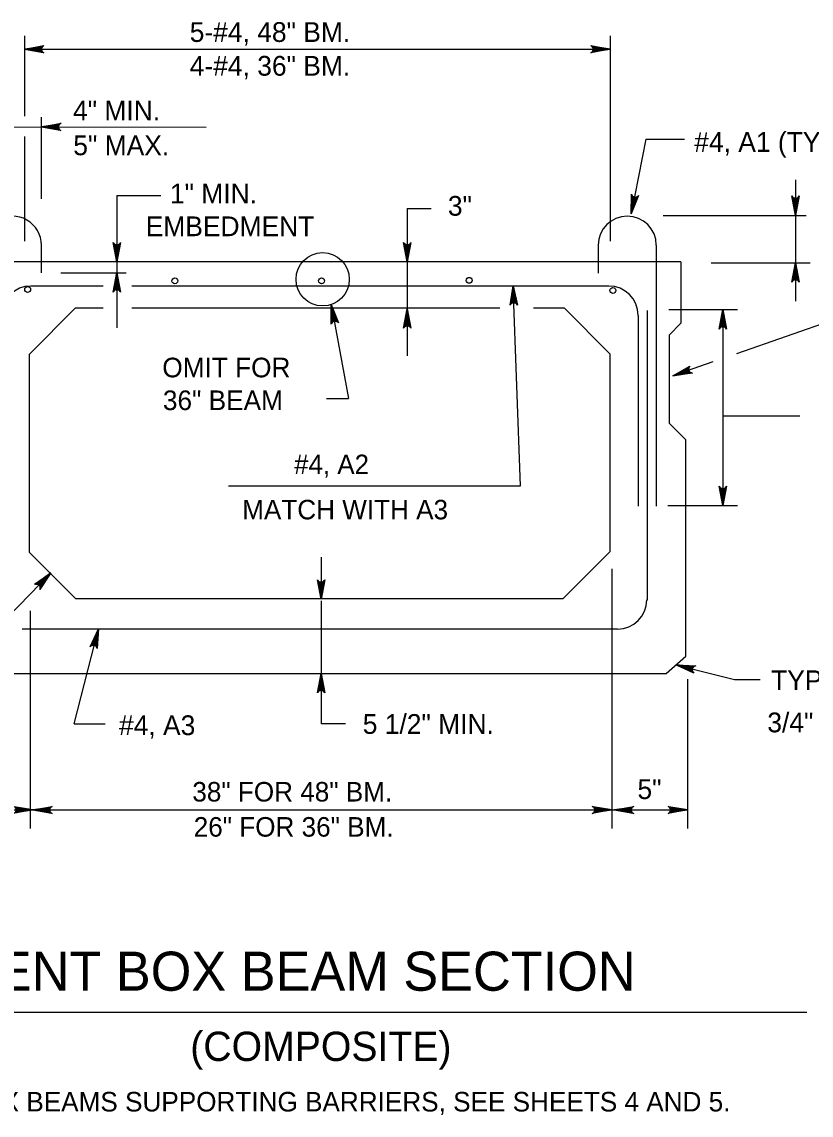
# Model space of a CAD drawing. Extents: x 639331 to 643089, y 299088 to 300975.
# Drawn here: x 640804.7 to 640925.9, y 299972.3 to 300140.1 of the extents above; entities that cross this region are included whole.
import ezdxf

# ---------------------------------------------------------------- set-up
doc = ezdxf.new("R2010")
doc.units = 0
doc.layers.add('1', color=7, linetype='Continuous')

msp = doc.modelspace()

# ---------------------------------------------------------------- linework, layer by layer
at = {"layer": '1'}
for p, q in [((640805.1, 300137.92), (640805.1, 300125.6)), ((640895.02, 300137.92), (640895.02, 300106.4)), ((640805.1, 300135.87), (640895.02, 300135.87)), ((640807.7, 300112.91), (640807.72, 300125.45)), ((640790.04, 300123.99), (640833.01, 300123.91)), ((640805.1, 300122.51), (640805.1, 300106.4)), ((640900.5, 300122.06), (640898.25, 300110.62)), ((640900.5, 300122.06), (640906.42, 300122.06)), ((640923.49, 300115.86), (640923.49, 300110.38)), ((640819.29, 300113.41), (640826.03, 300113.41)), ((640819.29, 300113.41), (640819.29, 300101.58)), ((640863.88, 300111.46), (640867.54, 300111.46)), ((640863.88, 300111.46), (640863.88, 300103.25)), ((640903.15, 300110.38), (640925.12, 300110.38)), ((640923.49, 300110.38), (640923.49, 300103.12)), ((640807.68, 300105.81), (640807.68, 300101.58)), ((640893.19, 300105.82), (640893.19, 300101.53)), ((640902.11, 300105.81), (640902.11, 300065.74)), ((640905.9, 300103.25), (640794.85, 300103.25)), ((640863.88, 300103.25), (640863.88, 300096.17)), ((640905.9, 300103.25), (640905.9, 300093.82)), ((640910.56, 300103.12), (640925.73, 300103.12)), ((640923.49, 300103.12), (640923.49, 300097.21)), ((640810.68, 300101.58), (640820.72, 300101.58)), ((640819.29, 300101.58), (640819.29, 300093.14)), ((640828.21, 300100.67), (640828.21, 300100.67)), ((640850.82, 300100.55), (640850.82, 300100.55)), ((640873.3, 300100.42), (640873.3, 300100.42)), ((640805.73, 300099.33), (640805.73, 300099.33)), ((640806.08, 300099.58), (640817.16, 300099.58)), ((640821.58, 300099.58), (640894.81, 300099.58)), ((640881.27, 300068.86), (640880.12, 300099.58)), ((640895.91, 300098.83), (640895.91, 300098.83)), ((640805.86, 300089.1), (640812.93, 300096.17)), ((640812.93, 300096.17), (640817.16, 300096.17)), ((640821.58, 300096.17), (640878.11, 300096.17)), ((640852.21, 300096.71), (640854.86, 300082.28)), ((640863.88, 300096.17), (640863.88, 300088.85)), ((640883.27, 300096.17), (640887.95, 300096.17)), ((640887.95, 300096.17), (640895.02, 300089.1)), ((640900.71, 300095.8), (640900.71, 300051.34)), ((640904.03, 300095.92), (640914.6, 300095.92)), ((640912.33, 300095.92), (640912.33, 300065.85)), ((640932.22, 300095.37), (640914.43, 300089.15)), ((640899.31, 300095.04), (640899.31, 300065.74)), ((640905.9, 300093.82), (640904.11, 300092.02)), ((640904.11, 300092.02), (640904.11, 300078.48)), ((640805.86, 300058.67), (640805.86, 300089.1)), ((640895.02, 300058.79), (640895.02, 300089.1)), ((640910.79, 300087.88), (640904.64, 300085.74)), ((640851.45, 300082.28), (640854.86, 300082.28)), ((640906.64, 300075.94), (640904.11, 300078.48)), ((640912.33, 300079.63), (640924.17, 300079.63)), ((640906.64, 300042.75), (640906.64, 300075.94)), ((640836.42, 300068.86), (640881.27, 300068.86)), ((640903.86, 300065.85), (640914.6, 300065.85)), ((640805.86, 300058.67), (640812.93, 300051.59)), ((640887.82, 300051.59), (640895.02, 300058.79)), ((640850.63, 300057.93), (640850.63, 300051.47)), ((640809.14, 300055.51), (640786.72, 300032.44)), ((640895.28, 300056.14), (640895.28, 300016.29)), ((640812.93, 300051.59), (640887.82, 300051.59)), ((640850.63, 300051.21), (640850.63, 300040.1)), ((640805.99, 300049.7), (640805.99, 300016.29)), ((640804.72, 300046.92), (640896.16, 300046.92)), ((640812.75, 300032.35), (640816.47, 300046.92)), ((640903.61, 300040.1), (640906.64, 300042.75)), ((640797.14, 300040.1), (640903.61, 300040.1)), ((640850.63, 300040.1), (640850.63, 300039.97)), ((640850.63, 300040.1), (640850.63, 300032.35)), ((640905.13, 300041.43), (640914.12, 300039.15)), ((640906.89, 300039.19), (640906.89, 300016.29)), ((640914.12, 300039.15), (640918.05, 300039.15)), ((640812.75, 300032.35), (640817.48, 300032.35)), ((640854.39, 300032.35), (640850.63, 300032.35)), ((640794.37, 300019.13), (640806.36, 300019.13)), ((640806.36, 300019.13), (640895.65, 300019.13)), ((640895.65, 300019.13), (640906.89, 300019.13)), ((640772.36, 299988.08), (640925.24, 299988.08))]:
    msp.add_line(p, q, dxfattribs=at)
for points in [[(640805.1, 300135.87), (640808.08, 300136.43), (640807.97, 300136.35), (640807.85, 300136.27), (640807.8, 300136.17), (640807.74, 300136.07), (640807.72, 300135.97), (640807.7, 300135.87), (640807.72, 300135.77), (640807.74, 300135.67), (640807.8, 300135.57), (640807.85, 300135.47), (640807.97, 300135.39), (640808.08, 300135.31), (640805.1, 300135.87), (640807.97, 300135.39), (640807.85, 300135.47), (640805.1, 300135.87), (640807.8, 300135.57), (640807.74, 300135.67), (640805.1, 300135.87), (640807.72, 300135.77), (640807.7, 300135.87), (640805.1, 300135.87), (640807.72, 300135.97), (640807.74, 300136.07), (640805.1, 300135.87), (640807.8, 300136.17), (640807.85, 300136.27), (640805.1, 300135.87), (640807.97, 300136.35)], [(640895.02, 300135.87), (640892.04, 300135.31), (640892.16, 300135.39), (640892.27, 300135.47), (640892.33, 300135.57), (640892.39, 300135.67), (640892.41, 300135.77), (640892.42, 300135.87), (640892.41, 300135.97), (640892.39, 300136.07), (640892.33, 300136.17), (640892.27, 300136.27), (640892.16, 300136.35), (640892.04, 300136.43), (640895.02, 300135.87), (640892.16, 300136.35), (640892.27, 300136.27), (640895.02, 300135.87), (640892.33, 300136.17), (640892.39, 300136.07), (640895.02, 300135.87), (640892.41, 300135.97), (640892.42, 300135.87), (640895.02, 300135.87), (640892.41, 300135.77), (640892.39, 300135.67), (640895.02, 300135.87), (640892.33, 300135.57), (640892.27, 300135.47), (640895.02, 300135.87), (640892.16, 300135.39)], [(640807.72, 300123.96), (640810.71, 300124.51), (640810.59, 300124.44), (640810.48, 300124.36), (640810.42, 300124.26), (640810.36, 300124.16), (640810.34, 300124.06), (640810.32, 300123.96), (640810.34, 300123.86), (640810.36, 300123.76), (640810.42, 300123.66), (640810.47, 300123.56), (640810.59, 300123.48), (640810.7, 300123.4), (640807.72, 300123.96), (640810.59, 300123.48), (640810.47, 300123.56), (640807.72, 300123.96), (640810.42, 300123.66), (640810.36, 300123.76), (640807.72, 300123.96), (640810.34, 300123.86), (640810.32, 300123.96), (640807.72, 300123.96), (640810.34, 300124.06), (640810.36, 300124.16), (640807.72, 300123.96), (640810.42, 300124.26), (640810.48, 300124.36), (640807.72, 300123.96), (640810.59, 300124.44)], [(640898.25, 300110.62), (640898.28, 300113.65), (640898.34, 300113.53), (640898.39, 300113.4), (640898.48, 300113.32), (640898.57, 300113.24), (640898.66, 300113.21), (640898.75, 300113.17), (640898.86, 300113.17), (640898.96, 300113.17), (640899.07, 300113.2), (640899.18, 300113.24), (640899.28, 300113.34), (640899.38, 300113.44), (640898.25, 300110.62), (640899.28, 300113.34), (640899.18, 300113.24), (640898.25, 300110.62), (640899.07, 300113.2), (640898.96, 300113.17), (640898.25, 300110.62), (640898.86, 300113.17), (640898.75, 300113.17), (640898.25, 300110.62), (640898.66, 300113.21), (640898.57, 300113.24), (640898.25, 300110.62), (640898.48, 300113.32), (640898.39, 300113.4), (640898.25, 300110.62), (640898.34, 300113.53)], [(640923.49, 300110.38), (640922.93, 300113.36), (640923.01, 300113.25), (640923.09, 300113.13), (640923.19, 300113.07), (640923.29, 300113.01), (640923.39, 300113), (640923.49, 300112.98), (640923.59, 300113), (640923.69, 300113.01), (640923.79, 300113.07), (640923.89, 300113.13), (640923.97, 300113.25), (640924.05, 300113.36), (640923.49, 300110.38), (640923.97, 300113.25), (640923.89, 300113.13), (640923.49, 300110.38), (640923.79, 300113.07), (640923.69, 300113.01), (640923.49, 300110.38), (640923.59, 300113), (640923.49, 300112.98), (640923.49, 300110.38), (640923.39, 300113), (640923.29, 300113.01), (640923.49, 300110.38), (640923.19, 300113.07), (640923.09, 300113.13), (640923.49, 300110.38), (640923.01, 300113.25)], [(640819.29, 300103.25), (640818.73, 300106.23), (640818.81, 300106.12), (640818.89, 300106), (640818.99, 300105.94), (640819.09, 300105.88), (640819.19, 300105.86), (640819.29, 300105.85), (640819.39, 300105.86), (640819.49, 300105.88), (640819.59, 300105.94), (640819.69, 300106), (640819.77, 300106.12), (640819.85, 300106.23), (640819.29, 300103.25), (640819.77, 300106.12), (640819.69, 300106), (640819.29, 300103.25), (640819.59, 300105.94), (640819.49, 300105.88), (640819.29, 300103.25), (640819.39, 300105.86), (640819.29, 300105.85), (640819.29, 300103.25), (640819.19, 300105.86), (640819.09, 300105.88), (640819.29, 300103.25), (640818.99, 300105.94), (640818.89, 300106), (640819.29, 300103.25), (640818.81, 300106.12)], [(640863.88, 300103.25), (640863.32, 300106.23), (640863.4, 300106.12), (640863.48, 300106), (640863.58, 300105.94), (640863.68, 300105.88), (640863.78, 300105.86), (640863.88, 300105.85), (640863.98, 300105.86), (640864.08, 300105.88), (640864.18, 300105.94), (640864.28, 300106), (640864.36, 300106.12), (640864.44, 300106.23), (640863.88, 300103.25), (640864.36, 300106.12), (640864.28, 300106), (640863.88, 300103.25), (640864.18, 300105.94), (640864.08, 300105.88), (640863.88, 300103.25), (640863.98, 300105.86), (640863.88, 300105.85), (640863.88, 300103.25), (640863.78, 300105.86), (640863.68, 300105.88), (640863.88, 300103.25), (640863.58, 300105.94), (640863.48, 300106), (640863.88, 300103.25), (640863.4, 300106.12)], [(640923.49, 300103.12), (640924.05, 300100.14), (640923.97, 300100.25), (640923.89, 300100.37), (640923.79, 300100.43), (640923.69, 300100.49), (640923.59, 300100.5), (640923.49, 300100.52), (640923.39, 300100.5), (640923.29, 300100.49), (640923.19, 300100.43), (640923.09, 300100.37), (640923.01, 300100.25), (640922.93, 300100.14), (640923.49, 300103.12), (640923.01, 300100.25), (640923.09, 300100.37), (640923.49, 300103.12), (640923.19, 300100.43), (640923.29, 300100.49), (640923.49, 300103.12), (640923.39, 300100.5), (640923.49, 300100.52), (640923.49, 300103.12), (640923.59, 300100.5), (640923.69, 300100.49), (640923.49, 300103.12), (640923.79, 300100.43), (640923.89, 300100.37), (640923.49, 300103.12), (640923.97, 300100.25)], [(640819.29, 300101.58), (640819.85, 300098.6), (640819.77, 300098.72), (640819.69, 300098.83), (640819.59, 300098.89), (640819.49, 300098.95), (640819.39, 300098.97), (640819.29, 300098.98), (640819.19, 300098.97), (640819.09, 300098.95), (640818.99, 300098.89), (640818.89, 300098.83), (640818.81, 300098.72), (640818.73, 300098.6), (640819.29, 300101.58), (640818.81, 300098.72), (640818.89, 300098.83), (640819.29, 300101.58), (640818.99, 300098.89), (640819.09, 300098.95), (640819.29, 300101.58), (640819.19, 300098.97), (640819.29, 300098.98), (640819.29, 300101.58), (640819.39, 300098.97), (640819.49, 300098.95), (640819.29, 300101.58), (640819.59, 300098.89), (640819.69, 300098.83), (640819.29, 300101.58), (640819.77, 300098.72)], [(640880.12, 300099.58), (640880.79, 300096.62), (640880.71, 300096.74), (640880.62, 300096.85), (640880.52, 300096.9), (640880.42, 300096.96), (640880.32, 300096.97), (640880.22, 300096.99), (640880.12, 300096.97), (640880.02, 300096.94), (640879.92, 300096.88), (640879.82, 300096.82), (640879.75, 300096.7), (640879.67, 300096.58), (640880.12, 300099.58), (640879.75, 300096.7), (640879.82, 300096.82), (640880.12, 300099.58), (640879.92, 300096.88), (640880.02, 300096.94), (640880.12, 300099.58), (640880.12, 300096.97), (640880.22, 300096.99), (640880.12, 300099.58), (640880.32, 300096.97), (640880.42, 300096.96), (640880.12, 300099.58), (640880.52, 300096.9), (640880.62, 300096.85), (640880.12, 300099.58), (640880.71, 300096.74)], [(640852.21, 300096.71), (640853.3, 300093.87), (640853.2, 300093.97), (640853.1, 300094.07), (640852.99, 300094.11), (640852.88, 300094.15), (640852.78, 300094.15), (640852.68, 300094.15), (640852.59, 300094.11), (640852.49, 300094.08), (640852.4, 300094), (640852.32, 300093.93), (640852.26, 300093.8), (640852.2, 300093.67), (640852.21, 300096.71), (640852.26, 300093.8), (640852.32, 300093.93), (640852.21, 300096.71), (640852.4, 300094), (640852.49, 300094.08), (640852.21, 300096.71), (640852.59, 300094.11), (640852.68, 300094.15), (640852.21, 300096.71), (640852.78, 300094.15), (640852.88, 300094.15), (640852.21, 300096.71), (640852.99, 300094.11), (640853.1, 300094.07), (640852.21, 300096.71), (640853.2, 300093.97)], [(640863.88, 300096.05), (640864.44, 300093.07), (640864.36, 300093.18), (640864.28, 300093.3), (640864.18, 300093.35), (640864.08, 300093.41), (640863.98, 300093.43), (640863.88, 300093.45), (640863.78, 300093.43), (640863.68, 300093.41), (640863.58, 300093.35), (640863.48, 300093.3), (640863.4, 300093.18), (640863.32, 300093.07), (640863.88, 300096.05), (640863.4, 300093.18), (640863.48, 300093.3), (640863.88, 300096.05), (640863.58, 300093.35), (640863.68, 300093.41), (640863.88, 300096.05), (640863.78, 300093.43), (640863.88, 300093.45), (640863.88, 300096.05), (640863.98, 300093.43), (640864.08, 300093.41), (640863.88, 300096.05), (640864.18, 300093.35), (640864.28, 300093.3), (640863.88, 300096.05), (640864.36, 300093.18)], [(640912.33, 300095.92), (640912.88, 300092.94), (640912.81, 300093.05), (640912.73, 300093.17), (640912.63, 300093.23), (640912.53, 300093.29), (640912.43, 300093.3), (640912.33, 300093.32), (640912.23, 300093.3), (640912.13, 300093.29), (640912.03, 300093.23), (640911.93, 300093.17), (640911.85, 300093.05), (640911.77, 300092.94), (640912.33, 300095.92), (640911.85, 300093.05), (640911.93, 300093.17), (640912.33, 300095.92), (640912.03, 300093.23), (640912.13, 300093.29), (640912.33, 300095.92), (640912.23, 300093.3), (640912.33, 300093.32), (640912.33, 300095.92), (640912.43, 300093.3), (640912.53, 300093.29), (640912.33, 300095.92), (640912.63, 300093.23), (640912.73, 300093.17), (640912.33, 300095.92), (640912.81, 300093.05)], [(640904.64, 300085.74), (640907.28, 300087.25), (640907.19, 300087.13), (640907.11, 300087.02), (640907.09, 300086.91), (640907.07, 300086.79), (640907.08, 300086.69), (640907.1, 300086.59), (640907.15, 300086.5), (640907.2, 300086.42), (640907.29, 300086.34), (640907.38, 300086.27), (640907.51, 300086.23), (640907.65, 300086.19), (640904.64, 300085.74), (640907.51, 300086.23), (640907.38, 300086.27), (640904.64, 300085.74), (640907.29, 300086.34), (640907.2, 300086.42), (640904.64, 300085.74), (640907.15, 300086.5), (640907.1, 300086.59), (640904.64, 300085.74), (640907.08, 300086.69), (640907.07, 300086.79), (640904.64, 300085.74), (640907.09, 300086.91), (640907.11, 300087.02), (640904.64, 300085.74), (640907.19, 300087.13)], [(640912.33, 300065.85), (640911.77, 300068.83), (640911.85, 300068.72), (640911.93, 300068.6), (640912.03, 300068.54), (640912.13, 300068.48), (640912.23, 300068.47), (640912.33, 300068.45), (640912.43, 300068.47), (640912.53, 300068.48), (640912.63, 300068.54), (640912.73, 300068.6), (640912.81, 300068.72), (640912.88, 300068.83), (640912.33, 300065.85), (640912.81, 300068.72), (640912.73, 300068.6), (640912.33, 300065.85), (640912.63, 300068.54), (640912.53, 300068.48), (640912.33, 300065.85), (640912.43, 300068.47), (640912.33, 300068.45), (640912.33, 300065.85), (640912.23, 300068.47), (640912.13, 300068.48), (640912.33, 300065.85), (640912.03, 300068.54), (640911.93, 300068.6), (640912.33, 300065.85), (640911.85, 300068.72)], [(640809.14, 300055.51), (640807.46, 300052.98), (640807.49, 300053.12), (640807.51, 300053.25), (640807.48, 300053.37), (640807.45, 300053.48), (640807.39, 300053.56), (640807.33, 300053.64), (640807.25, 300053.7), (640807.16, 300053.76), (640807.05, 300053.79), (640806.94, 300053.81), (640806.8, 300053.79), (640806.66, 300053.76), (640809.14, 300055.51), (640806.8, 300053.79), (640806.94, 300053.81), (640809.14, 300055.51), (640807.05, 300053.79), (640807.16, 300053.76), (640809.14, 300055.51), (640807.25, 300053.7), (640807.33, 300053.64), (640809.14, 300055.51), (640807.39, 300053.56), (640807.45, 300053.48), (640809.14, 300055.51), (640807.48, 300053.37), (640807.51, 300053.25), (640809.14, 300055.51), (640807.49, 300053.12)], [(640850.63, 300051.47), (640850.07, 300054.45), (640850.15, 300054.33), (640850.23, 300054.22), (640850.33, 300054.16), (640850.43, 300054.1), (640850.53, 300054.08), (640850.63, 300054.07), (640850.73, 300054.08), (640850.83, 300054.1), (640850.93, 300054.16), (640851.03, 300054.22), (640851.11, 300054.33), (640851.19, 300054.45), (640850.63, 300051.47), (640851.11, 300054.33), (640851.03, 300054.22), (640850.63, 300051.47), (640850.93, 300054.16), (640850.83, 300054.1), (640850.63, 300051.47), (640850.73, 300054.08), (640850.63, 300054.07), (640850.63, 300051.47), (640850.53, 300054.08), (640850.43, 300054.1), (640850.63, 300051.47), (640850.33, 300054.16), (640850.23, 300054.22), (640850.63, 300051.47), (640850.15, 300054.33)], [(640816.47, 300046.92), (640816.27, 300043.89), (640816.22, 300044.02), (640816.17, 300044.15), (640816.09, 300044.24), (640816.01, 300044.32), (640815.92, 300044.36), (640815.82, 300044.4), (640815.72, 300044.41), (640815.62, 300044.42), (640815.51, 300044.38), (640815.4, 300044.35), (640815.29, 300044.26), (640815.19, 300044.17), (640816.47, 300046.92), (640815.29, 300044.26), (640815.4, 300044.35), (640816.47, 300046.92), (640815.51, 300044.38), (640815.62, 300044.42), (640816.47, 300046.92), (640815.72, 300044.41), (640815.82, 300044.4), (640816.47, 300046.92), (640815.92, 300044.36), (640816.01, 300044.32), (640816.47, 300046.92), (640816.09, 300044.24), (640816.17, 300044.15), (640816.47, 300046.92), (640816.22, 300044.02)], [(640850.63, 300040.1), (640851.19, 300037.12), (640851.11, 300037.23), (640851.03, 300037.35), (640850.93, 300037.41), (640850.83, 300037.47), (640850.73, 300037.48), (640850.63, 300037.5), (640850.53, 300037.48), (640850.43, 300037.47), (640850.33, 300037.41), (640850.23, 300037.35), (640850.15, 300037.23), (640850.07, 300037.12), (640850.63, 300040.1), (640850.15, 300037.23), (640850.23, 300037.35), (640850.63, 300040.1), (640850.33, 300037.41), (640850.43, 300037.47), (640850.63, 300040.1), (640850.53, 300037.48), (640850.63, 300037.5), (640850.63, 300040.1), (640850.73, 300037.48), (640850.83, 300037.47), (640850.63, 300040.1), (640850.93, 300037.41), (640851.03, 300037.35), (640850.63, 300040.1), (640851.11, 300037.23)], [(640905.13, 300041.43), (640908.16, 300041.24), (640908.03, 300041.19), (640907.89, 300041.14), (640907.81, 300041.06), (640907.73, 300040.97), (640907.69, 300040.88), (640907.65, 300040.79), (640907.64, 300040.69), (640907.63, 300040.59), (640907.67, 300040.48), (640907.7, 300040.36), (640907.79, 300040.26), (640907.88, 300040.15), (640905.13, 300041.43), (640907.79, 300040.26), (640907.7, 300040.36), (640905.13, 300041.43), (640907.67, 300040.48), (640907.63, 300040.59), (640905.13, 300041.43), (640907.64, 300040.69), (640907.65, 300040.79), (640905.13, 300041.43), (640907.69, 300040.88), (640907.73, 300040.97), (640905.13, 300041.43), (640907.81, 300041.06), (640907.89, 300041.14), (640905.13, 300041.43), (640908.03, 300041.19)], [(640803.38, 300019.69), (640806.36, 300019.13), (640803.5, 300019.61)], [(640806.36, 300019.13), (640809.35, 300019.69), (640809.23, 300019.61), (640809.12, 300019.53), (640809.06, 300019.43), (640809, 300019.33), (640808.98, 300019.23), (640808.96, 300019.13), (640808.98, 300019.03), (640809, 300018.93), (640809.06, 300018.83), (640809.12, 300018.73), (640809.23, 300018.65), (640809.35, 300018.57), (640806.36, 300019.13), (640809.23, 300018.65), (640809.12, 300018.73), (640806.36, 300019.13), (640809.06, 300018.83), (640809, 300018.93), (640806.36, 300019.13), (640808.98, 300019.03), (640808.96, 300019.13), (640806.36, 300019.13), (640808.98, 300019.23), (640809, 300019.33), (640806.36, 300019.13), (640809.06, 300019.43), (640809.12, 300019.53), (640806.36, 300019.13), (640809.23, 300019.61)], [(640895.28, 300019.13), (640892.29, 300018.57), (640892.41, 300018.65), (640892.52, 300018.73), (640892.58, 300018.83), (640892.64, 300018.93), (640892.66, 300019.03), (640892.68, 300019.13), (640892.66, 300019.23), (640892.64, 300019.33), (640892.58, 300019.43), (640892.52, 300019.53), (640892.41, 300019.61), (640892.29, 300019.69), (640895.28, 300019.13), (640892.41, 300019.61), (640892.52, 300019.53), (640895.28, 300019.13), (640892.58, 300019.43), (640892.64, 300019.33), (640895.28, 300019.13), (640892.66, 300019.23), (640892.68, 300019.13), (640895.28, 300019.13), (640892.66, 300019.03), (640892.64, 300018.93), (640895.28, 300019.13), (640892.58, 300018.83), (640892.52, 300018.73), (640895.28, 300019.13), (640892.41, 300018.65)], [(640895.65, 300019.13), (640898.64, 300019.69), (640898.52, 300019.61), (640898.41, 300019.53), (640898.35, 300019.43), (640898.29, 300019.33), (640898.27, 300019.23), (640898.26, 300019.13), (640898.27, 300019.03), (640898.29, 300018.93), (640898.35, 300018.83), (640898.41, 300018.73), (640898.52, 300018.65), (640898.64, 300018.57), (640895.65, 300019.13), (640898.52, 300018.65), (640898.41, 300018.73), (640895.65, 300019.13), (640898.35, 300018.83), (640898.29, 300018.93), (640895.65, 300019.13), (640898.27, 300019.03), (640898.26, 300019.13), (640895.65, 300019.13), (640898.27, 300019.23), (640898.29, 300019.33), (640895.65, 300019.13), (640898.35, 300019.43), (640898.41, 300019.53), (640895.65, 300019.13), (640898.52, 300019.61)], [(640906.89, 300019.13), (640903.91, 300018.57), (640904.03, 300018.65), (640904.14, 300018.73), (640904.2, 300018.83), (640904.26, 300018.93), (640904.28, 300019.03), (640904.29, 300019.13), (640904.28, 300019.23), (640904.26, 300019.33), (640904.2, 300019.43), (640904.14, 300019.53), (640904.03, 300019.61), (640903.91, 300019.69), (640906.89, 300019.13), (640904.03, 300019.61), (640904.14, 300019.53), (640906.89, 300019.13), (640904.2, 300019.43), (640904.26, 300019.33), (640906.89, 300019.13), (640904.28, 300019.23), (640904.29, 300019.13), (640906.89, 300019.13), (640904.28, 300019.03), (640904.26, 300018.93), (640906.89, 300019.13), (640904.2, 300018.83), (640904.14, 300018.73), (640906.89, 300019.13), (640904.03, 300018.65)], [(640806.36, 300019.13), (640803.38, 300018.57)], [(640803.61, 300018.73), (640806.36, 300019.13), (640803.5, 300018.65)], [(640803.61, 300019.53), (640806.36, 300019.13), (640803.67, 300019.43)], [(640803.73, 300018.93), (640806.36, 300019.13), (640803.67, 300018.83)], [(640803.73, 300019.33), (640806.36, 300019.13), (640803.75, 300019.23)], [(640803.76, 300019.13), (640806.36, 300019.13), (640803.75, 300019.03)]]:
    msp.add_lwpolyline(points, dxfattribs=at)
for centre, radius in [((640850.88, 300100.57), 4.09), ((640828.19, 300100.33), 0.452), ((640850.72, 300100.33), 0.452), ((640873.38, 300100.41), 0.452), ((640805.58, 300099.01), 0.452), ((640895.45, 300098.86), 0.452)]:
    msp.add_circle(centre, radius, dxfattribs=at)
for centre, radius, start, end in [((640803.23, 300105.81), 4.46, 359.9442, 180.0003), ((640897.65, 300105.81), 4.46, 0, 179.9443), ((640806.08, 300095.04), 4.5, 90, 180), ((640894.81, 300095.04), 4.5, 0, 90), ((640896.15, 300051.38), 4.5, 270, 360)]:
    msp.add_arc(centre, radius, start, end, dxfattribs=at)

# ---------------------------------------------------------------- texts
for s, height, p in [('5-#4, 48" BM.', 3.0311, (640830.47, 300137)), ('4-#4, 36" BM.', 3.0311, (640830.47, 300131.82)), ('#4, A1 (TYP.)', 3.0311, (640907.94, 300120.13)), ('1" MIN.', 3.031, (640827.43, 300112.22)), ('3"', 3.031, (640870.11, 300110.33)), ('EMBEDMENT', 3.031, (640823.71, 300107.19)), ('OMIT FOR', 3.01, (640826.26, 300085.53)), ('36" BEAM', 3.01, (640826.35, 300080.5)), ('#4, A2', 2.975, (640846.5, 300070.69)), ('MATCH WITH A3', 2.9962, (640838.53, 300063.73)), ('TYP. CHAMFER:', 3.0311, (640919.74, 300037.52)), ('#4, A3', 3.031, (640819.61, 300030.62)), ('5 1/2" MIN.', 3.0311, (640857.04, 300030.81)), ('3/4" x 3/4"', 3.0311, (640919.16, 300031.05)), ('38" FOR 48" BM.', 2.9977, (640830.87, 300020.43)), ('5"', 3.031, (640899.22, 300020.81)), ('26" FOR 36" BM.', 2.9977, (640831.08, 300015.04)), ('ADJACENT BOX BEAM SECTION', 6, (640774.55, 299991.39)), ('(COMPOSITE)', 4.5, (640830.55, 299980.61)), ('FOR ADJACENT BOX BEAMS SUPPORTING BARRIERS, SEE SHEETS 4 AND 5.', 3, (640763.92, 299972.86))]:
    msp.add_text(s, height=height, dxfattribs=at).set_placement(p)
for s, p in [('4" MIN.', (640812.55, 300124.95)), ('5" MAX.', (640812.59, 300119.61))]:
    msp.add_text(s, height=3.031, rotation=360, dxfattribs=at).set_placement(p)

doc.saveas('drawing.dxf')
